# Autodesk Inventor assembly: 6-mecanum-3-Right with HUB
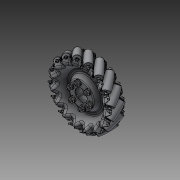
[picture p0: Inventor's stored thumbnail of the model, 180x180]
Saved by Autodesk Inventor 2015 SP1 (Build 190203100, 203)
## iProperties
Created: 2015-01
Part Number: 6-mecanum-3-Right with HUB
Document SubType Name: Assembly
Designer: TODD D MILLER
Mass: 713.537 g
Surface Area: 1552.75 cm^2
Volume: 208.67 cm^3
Density: 3.41946 g/cm^3
Author: TODD D MILLER
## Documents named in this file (4)
- C:\Users\TODD D MILLER\Documents\GrabCAD\ElkLogics FRC\CAD Library\Mecanum wheels\6-mecanum-3-Right with HUB.iam
- C:\Users\TODD D MILLER\Documents\GrabCAD\ElkLogics FRC\CAD Library\Mecanum wheels\500EX-Key-Hub.ipt
- C:\Users\TODD D MILLER\Documents\GrabCAD\ElkLogics FRC\CAD Library\Mecanum wheels\6-mecanum-3-Left with HUB\Design Accelerator\Bolted Connection1.iam
- C:\Users\TODD D MILLER\Documents\GrabCAD\ElkLogics FRC\CAD Library\Mecanum wheels\6-mecanum-3-Right.iam
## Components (3 placed, 3 different names)
1. 6-mecanum-3-Right:1 [sub-assembly] — Insert:1, Insert:2
2. 500EX-Key-Hub:1 — Insert:1, Insert:2, Mate:2, Mate:3
3. Bolted Connection:1 [sub-assembly] — Mate:2, Mate:3
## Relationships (4: Insert 2, Mate 2)
- Insert:1: 6-mecanum-3-Right:1 ↔ 500EX-Key-Hub:1
- Insert:2: 6-mecanum-3-Right:1 ↔ 500EX-Key-Hub:1
- Mate:2: 500EX-Key-Hub:1 ↔ Bolted Connection:1
- Mate:3: 500EX-Key-Hub:1 ↔ Bolted Connection:1
